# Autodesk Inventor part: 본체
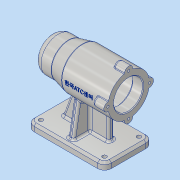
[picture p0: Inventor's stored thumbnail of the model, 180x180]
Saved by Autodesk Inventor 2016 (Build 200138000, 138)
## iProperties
Created: 2019-07
Part Number: 본체
Material: 알루미늄 6061
Document SubType Name: Modeling
Designer: MIRAE
Density: 2.7 g/cm^3
Appearance: 알루미늄 - 평지
Mass: 640.582 g
Surface Area: 654.192 cm^2
Volume: 237.253 cm^3
Author: MIRAE
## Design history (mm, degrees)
sketch "스케치1"
  geometry: L1 (-56, -35)-(56, -35); L2 (56, -35)-(56, 35); L3 (56, 35)-(-56, 35); L4 (-56, 35)-(-56, -35); L5 (-56, -35)-(56, 35); L6 (56, -35)-(-56, 35); 1 further point
  constraints: 12 end point, 2 midpoint, 2 parallel, 1 horizontal, 1 perpendicular
  dimensions: "d0" = 112 distance of L2.end L3.end; "d1" = 70 distance of L1.end L2.end
extrude "돌출1" new body sketch "스케치1" distance "d2" = 10; taper "d3" = 0 deg
sketch "스케치2"
  geometry: L1 (0, 35)-(-80, 35); C1 r 30 at (-80, 35)
  constraints: 2 end point, 1 centre point, 1 coincident, 1 horizontal
  dimensions: "d4" = 80 distance of L1.start L1.end; "d6" = 60 diameter of C1
extrude "돌출2" join sketch "스케치2" distance "d7" = 67; taper "d8" = 0 deg
node "작업 평면1"
sketch "스케치3"
  geometry: C1 r 25 at (0, 0); 1 further point
  constraints: 1 centre point
  dimensions: "d10" = 50 diameter of C1
feature "로프트1" dims "d11" = 0, "d12" = 90 deg, "d13" = 0, "d14" = 90 deg
  node "모서리1"
sketch "스케치5"
  geometry: C1 r 25 at (0, 0) reference; 1 further point
extrude "돌출3" join sketch "스케치5" distance "d16" = 25; taper "d17" = 0 deg
sketch "스케치6"
  geometry: C1 r 6 at (-30, 0); C2 r 6 at (0, 30); C3 r 6 at (30, 0); C4 r 6 at (0, -30); A1 r 30 centre (0, 0) between (-30, 0) and (0, 30) reference; 1 further point
  constraints: 4 centre point, 4 point on circle
  dimensions: "d18" = 12 diameter of C1; "d19" = 12 diameter of C2; "d20" = 12 diameter of C3; "d21" = 12 diameter of C4
extrude "돌출4" join sketch "스케치6" distance "d22" = 16; taper "d23" = 0 deg
sketch "스케치7"
  geometry: C1 r 25 at (-80, 35) reference; C2 r 21 at (-80, 35); 1 further point
  constraints: 1 centre point, 1 coincident
  dimensions: "d24" = 42 diameter of C2
extrude "돌출5" cut sketch "스케치7" distance "d25" = 15; taper "d26" = 0 deg
sketch "스케치8"
  geometry: C1 r 24 at (0, 0); 1 further point
  constraints: 1 centre point
  dimensions: "d27" = 48 diameter of C1
extrude "돌출6" cut sketch "스케치8" distance "d28" = 54; taper "d29" = 0 deg
sketch "스케치9"
  geometry: C1 r 21 at (0, 0); 1 further point
  constraints: 1 centre point
  dimensions: "d30" = 42 diameter of C1
extrude "돌출7" cut sketch "스케치9" distance "d31" = 12; taper "d32" = 0 deg
sketch "스케치10"
  geometry: C1 r 17.5 at (0, 0); 1 further point
  constraints: 1 centre point
  dimensions: "d33" = 35 diameter of C1
extrude "돌출8" cut sketch "스케치10" distance "d34" = 18; taper "d35" = 0 deg
sketch "스케치11"
  geometry: C1 r 16 at (0, 0); 1 further point
  constraints: 1 centre point
  dimensions: "d36" = 32 diameter of C1
extrude "돌출9" cut sketch "스케치11" distance "d37" = 4; taper "d38" = 0 deg
sketch "스케치12"
  geometry: C1 r 17.5 at (0, 0) reference; C2 r 10.5 at (0, 0); 1 further point
  constraints: 1 centre point, 1 coincident
  dimensions: "d39" = 21 diameter of C2
extrude "돌출10" cut sketch "스케치12" distance "d40" = 3; taper "d41" = 0 deg
sketch "스케치13"
  geometry: L1 (0, 4)-(31, 4); L2 (31, 4)-(31, -4); L3 (31, -4)-(0, -4); L4 (0, -4)-(0, 4); L5 (56, -35)-(56, 35) reference; 2 further points
  constraints: 8 end point, 2 parallel, 1 coincident, 1 horizontal, 1 midpoint, 1 perpendicular
  dimensions: "d43" = 8 distance of L1.end L2.end; "d44" = 25 distance between parallel lines of L5 L2
extrude "돌출11" join sketch "스케치13" stored distance "d45" = 3; taper "d46" = 0 deg
sketch "스케치14"
  geometry: L1 (-56, 10)-(56, 10) reference; L2 (56, 10)-(36, 10); L3 (36, 10)-(23.527, 44.27); 1 further point
  constraints: 4 end point, 1 point on line
  dimensions: "d47" = 20 distance of L1.end L2.end; "d48" = 110 deg angle of L1 L3
feature "리브1" sketch "스케치14" dims "d49" = 1, "d50" = 8, "d51" = 0, "d52" = 0, "d53" = 1, "d54" = 1
sketch "스케치15"
  geometry: L1 (-35, 0)-(-35, 10) reference; L2 (-35, 10)-(-28, 10); L3 (35, 10)-(-35, 10) reference; L4 (-28, 10)-(-21.375, 47.574); 1 further point
  constraints: 4 end point, 1 point on line
  dimensions: "d55" = 7 distance of L1.end L2.end; "d56" = 100 deg angle of L2 L4
feature "리브2" sketch "스케치15" dims "d57" = 1, "d58" = 8, "d59" = 0, "d60" = 0, "d61" = 1, "d62" = 1
fillet "모깎기1" dims "d65" = 3
fillet "모깎기2" dims "d66" = 0.3
chamfer "모따기1" distance "d67" = 1; stored, may be unused: second distance "d68" = 2, angle "d69" = 45 deg
fillet "모깎기3" dims "d70" = 3
fillet "모깎기4" dims "d71" = 10
fillet "모깎기5" dims "d72" = 3
fillet "모깎기6" dims "d73" = 3
fillet "모깎기7" dims "d74" = 3
fillet "모깎기8" dims "d75" = 1
chamfer "모따기2" distance "d76" = 3; stored, may be unused: second distance "d77" = 2, angle "d78" = 45 deg
fillet "모깎기9" dims "d79" = 3
sketch "스케치17"
  geometry: A1 r 10 centre (-46, 25) between (-46, 35) and (-56, 25) reference; A2 r 10 centre (-46, -25) between (-56, -25) and (-46, -35) reference; A3 r 10 centre (46, -25) between (46, -35) and (56, -25) reference; A4 r 10 centre (46, 25) between (56, 25) and (46, 35) reference; 5 further points
  constraints: 4 coincident
hole "구멍1" sketch "스케치17" at (-46, 25), (-46, -25), (46, -25), (46, 25) diameter "d80" = 6; stored, may be unused: countersink angle "d84" = 90 deg, drill point angle "d86" = 118 deg; dims "d81" = 6, "d82" = 4, "d83" = 2, "d85" = 8
sketch "스케치18"
  geometry: A1 r 6 centre (-110, 35) between (-110.171, 40.998) and (-110.171, 29.002) reference; A2 r 6 centre (-80, 65) between (-74.002, 65.171) and (-85.998, 65.171) reference; A3 r 6 centre (-50, 35) between (-49.829, 29.002) and (-49.829, 40.998) reference; A4 r 6 centre (-80, 5) between (-85.998, 4.829) and (-74.002, 4.829) reference; 5 further points
  constraints: 4 coincident
hole "구멍2" sketch "스케치18" at (-110, 35), (-80, 65), (-50, 35), (-80, 5) diameter "d87" = 3.242; stored, may be unused: countersink angle "d91" = 90 deg, drill point angle "d93" = 118 deg; dims "d88" = 8, "d89" = 4, "d90" = 2, "d92" = 11
node "작업 평면2"
sketch "스케치19"
  geometry: L1 (0, 5.998)-(0, -5.998) reference; L2 (0, 36)-(0, 30.171) reference; 3 further points
  constraints: 1 horizontal alignment, 1 midpoint, 1 other
  dimensions: "d94" = 42 distance from line of L2 point (-42, 0)
feature "엠보싱1" sketch "스케치19" dims "d95" = 0.5, "d96" = 0
feature "분할1"
node "솔리드1"
mirror "대칭1"
node "투영된 루프1"
